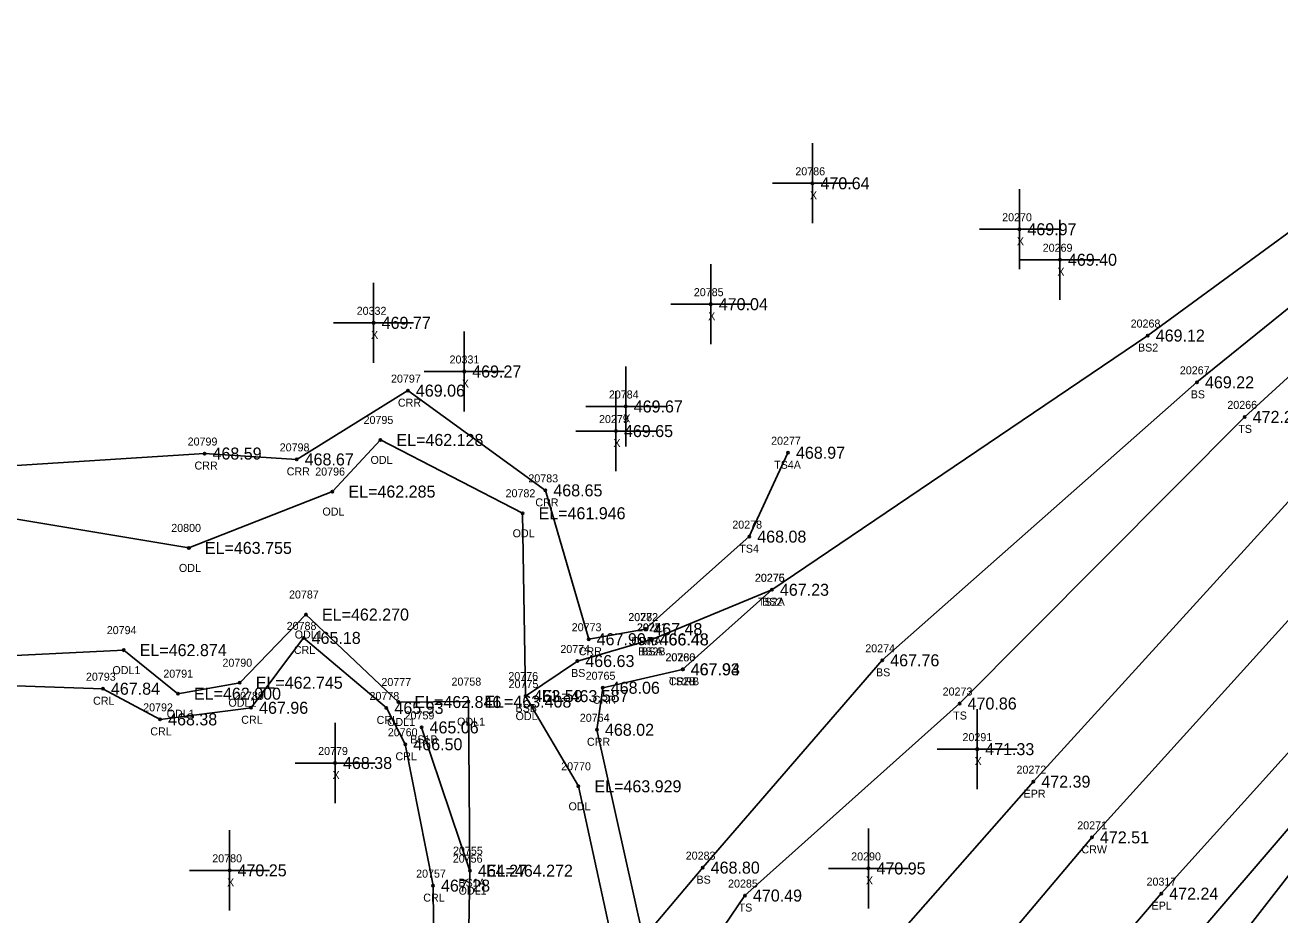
# Model space of a CAD drawing. Extents: x 1741010 to 1742139, y 749382 to 750625.
# Drawn here: x 1741509 to 1741665.8, y 750105.8 to 750217 of the extents above; entities that cross this region are included whole.
import ezdxf

# ---------------------------------------------------------------- set-up
doc = ezdxf.new("R2010")
doc.units = 0
for name, color, linetype in [('RD_DTM_BkLn1', 7, 'Continuous'), ('RD_DTM_BkLn2', 7, 'Continuous'), ('RD_DTM_BkLn_txCode', 7, 'Continuous'), ('RD_EX_H2O', 7, 'Continuous'), ('RD_EX_H2O_txCode', 7, 'Continuous'), ('RD_EX_Misc', 7, 'Continuous'), ('RD_EX_Misc_txCode', 7, 'Continuous'), ('RD_EX_Road', 7, 'Continuous'), ('RD_EX_Road_txCode', 7, 'Continuous'), ('RD_EX_TX_H2O_ELEV', 7, 'Continuous'), ('RD_EX_TX_Misc_ELEV', 7, 'Continuous'), ('RD_EX_TX_Road_ELEV', 7, 'Continuous'), ('RD_HC_Survey_ELEV', 7, 'Continuous'), ('RD_HC_Survey_txCode', 7, 'Continuous'), ('RD_SMD_Locator', 7, 'Continuous')]:
    doc.layers.add(name, color=color, linetype=linetype)

msp = doc.modelspace()

# ---------------------------------------------------------------- linework, layer by layer
at = {"layer": 'RD_DTM_BkLn1'}
msp.add_lwpolyline([(1742095.1, 750579.47), (1742056.96, 750547.11), (1742019.74, 750514.22), (1741983.45, 750480.17), (1741948.01, 750445.01), (1741913.15, 750409.3), (1741879.03, 750372.99), (1741811.59, 750300.09), (1741743.65, 750226.52), (1741676.29, 750153.06), (1741642.32, 750115.53), (1741610.32, 750077.63)], dxfattribs=at)
at = {"layer": 'RD_DTM_BkLn2'}
for p, q in [((1741602.32, 750146.46), (1741591.19, 750136.53)), ((1741564.57, 750111.37), (1741558.53, 750129.27))]:
    msp.add_line(p, q, dxfattribs=at)
for points in [[(1742105.6, 750567.48), (1742094.25, 750560.49), (1742091.64, 750555.7), (1742067.93, 750534.94), (1742031.73, 750501.95), (1741994.85, 750467.63), (1741959.82, 750432.06), (1741925.8, 750396.31), (1741891.25, 750362.62), (1741824.36, 750287.7), (1741756.44, 750214.6), (1741688.69, 750142.04), (1741655.55, 750103.43), (1741644.64, 750083.31), (1741626.06, 750060.3), (1741620, 750055.3), (1741614.97, 750059.12), (1741617.5, 750064.27), (1741619.23, 750067.96)], [(1742107.37, 750564.98), (1742099.21, 750558.66), (1742095.99, 750559.5), (1742095.15, 750554.39), (1742069.73, 750532.61), (1742034.06, 750499.81), (1741997.6, 750464.99), (1741961.88, 750429.54), (1741928.13, 750394.17), (1741895.34, 750359.02), (1741826.5, 750286.36), (1741758.73, 750213.29), (1741690.1, 750140.59), (1741658.36, 750099.77), (1741650.43, 750077.87), (1741632.9, 750061.59), (1741621.97, 750051.56), (1741618.99, 750048.78), (1741611.88, 750047.79)], [(1741687.02, 750214.18), (1741699.03, 750211.31), (1741701.37, 750206.33), (1741693.87, 750197.73), (1741661.42, 750168.06), (1741625.78, 750132.25), (1741598.95, 750108.26), (1741594.55, 750101.81), (1741595.44, 750091.73), (1741598, 750085.41), (1741619.23, 750067.96)], [(1741697.46, 750209.37), (1741696.69, 750207.39), (1741687.32, 750198.15), (1741655.45, 750172.38), (1741616.11, 750137.65), (1741593.67, 750111.75), (1741586.25, 750102.97)], [(1741697.46, 750209.37), (1741695.29, 750209.13), (1741682.34, 750202.39), (1741649.3, 750178.22), (1741602.32, 750146.46), (1741587.3, 750140.26)], [(1741604.33, 750163.58), (1741599.49, 750153.1), (1741586.49, 750141.54)], [(1741587.27, 750140.26), (1741578, 750137.56), (1741571.53, 750133.18)]]:
    msp.add_lwpolyline(points, dxfattribs=at)
at = {"layer": 'RD_EX_H2O'}
for points in [[(1741577.19, 750059.87), (1741574.31, 750069.19), (1741563.25, 750082.19), (1741560.12, 750095.32), (1741559.96, 750109.5), (1741556.5, 750127.16), (1741554.14, 750131.7), (1741543.79, 750140.45), (1741537.22, 750131.72), (1741525.85, 750130.27), (1741518.7, 750134.1), (1741490.89, 750135.06), (1741436.94, 750142.19), (1741375.71, 750163.12), (1741339.37, 750188.79), (1741331.64, 750190.2), (1741328.64, 750186.11), (1741320.24, 750158.32), (1741318.27, 750146.83), (1741309.48, 750135.97), (1741304.66, 750127.91)], [(1741586.49, 750141.56), (1741579.42, 750140.28), (1741574, 750158.88), (1741556.82, 750171.34), (1741542.92, 750162.75), (1741531.4, 750163.48), (1741496.74, 750161.28)], [(1741614.56, 750040.31), (1741609.32, 750045.96), (1741610.78, 750055.8), (1741591.38, 750076.1), (1741585.44, 750084.46), (1741582.64, 750101.29), (1741578.14, 750121.91), (1741571.53, 750133.18), (1741571.15, 750156.02), (1741553.39, 750165.18), (1741547.39, 750158.73), (1741529.44, 750151.69), (1741495.88, 750157.28)], [(1741605.22, 750035.39), (1741604.28, 750042.48), (1741585.13, 750064.77), (1741582.99, 750072.66), (1741567.25, 750084.11), (1741564.22, 750092.13), (1741564.57, 750111.37), (1741564.38, 750132.49), (1741555.63, 750132.44), (1741544.08, 750143.37), (1741535.8, 750134.85), (1741528.08, 750133.48), (1741521.3, 750138.92), (1741491.52, 750137.44)], [(1741597.3, 750084.84), (1741591, 750089.11), (1741586.21, 750103), (1741580.45, 750128.97), (1741581.18, 750134.22), (1741591.16, 750136.52)]]:
    msp.add_lwpolyline(points, dxfattribs=at)
at = {"layer": 'RD_EX_Misc'}
for p, q in [((1741607.39, 750192.24), (1741607.39, 750202.24)), ((1741602.39, 750197.24), (1741612.39, 750197.24)), ((1741633.26, 750186.5), (1741633.26, 750196.5)), ((1741628.26, 750191.5), (1741638.26, 750191.5)), ((1741638.32, 750182.69), (1741638.32, 750192.69)), ((1741594.68, 750177.14), (1741594.68, 750187.14)), ((1741633.32, 750187.69), (1741643.32, 750187.69)), ((1741552.54, 750174.81), (1741552.54, 750184.81)), ((1741589.68, 750182.14), (1741599.68, 750182.14)), ((1741547.54, 750179.81), (1741557.54, 750179.81)), ((1741563.86, 750168.73), (1741563.86, 750178.73)), ((1741584.05, 750164.36), (1741584.05, 750174.36)), ((1741558.86, 750173.73), (1741568.86, 750173.73)), ((1741582.83, 750161.29), (1741582.83, 750171.29)), ((1741579.05, 750169.36), (1741589.05, 750169.36)), ((1741577.83, 750166.29), (1741587.83, 750166.29)), ((1741627.98, 750121.55), (1741627.98, 750131.55)), ((1741547.71, 750119.82), (1741547.71, 750129.82)), ((1741622.98, 750126.55), (1741632.98, 750126.55)), ((1741542.71, 750124.82), (1741552.71, 750124.82)), ((1741534.53, 750106.41), (1741534.53, 750116.41)), ((1741614.39, 750106.65), (1741614.39, 750116.65)), ((1741529.53, 750111.41), (1741539.53, 750111.41)), ((1741609.39, 750111.65), (1741619.39, 750111.65))]:
    msp.add_line(p, q, dxfattribs=at)
at = {"layer": 'RD_EX_Road'}
for points in [[(1742095.24, 750593.27), (1742088.27, 750587.97), (1742078.23, 750580.89), (1742049.13, 750555.21), (1742012.94, 750522.73), (1741975.54, 750488.03), (1741940.71, 750452.82), (1741916.22, 750428.67), (1741904.72, 750416.99), (1741884.38, 750395.02), (1741870.75, 750380.27), (1741817.36, 750322.98), (1741803.89, 750307.66), (1741783.86, 750287.33), (1741735.44, 750234.07), (1741718.84, 750214.98), (1741710.25, 750205.58), (1741668.97, 750159.8), (1741635, 750122.49), (1741604.35, 750087.7), (1741600.63, 750085.47)], [(1742102.43, 750570.61), (1742093.26, 750562.71), (1742064.72, 750538.42), (1742027.92, 750505.65), (1741991.25, 750471.83), (1741956.32, 750436.98), (1741921.43, 750401.39), (1741886.79, 750364.93), (1741819.64, 750292.67), (1741751.78, 750219.01), (1741684.42, 750145.59), (1741650.98, 750108.5), (1741637.17, 750092.42), (1741621.17, 750073.94), (1741621.31, 750072.22), (1741619.24, 750070.27)]]:
    msp.add_lwpolyline(points, dxfattribs=at)
at = {"layer": 'RD_SMD_Locator'}
for centre in [(1741607.39, 750197.24), (1741633.26, 750191.5), (1741638.32, 750187.69), (1741594.68, 750182.14), (1741552.54, 750179.81), (1741649.3, 750178.22), (1741563.86, 750173.73), (1741655.45, 750172.38), (1741556.82, 750171.34), (1741584.05, 750169.36), (1741661.42, 750168.06), (1741582.83, 750166.29), (1741553.39, 750165.18), (1741531.4, 750163.48), (1741604.33, 750163.58), (1741542.92, 750162.75), (1741547.39, 750158.73), (1741574, 750158.88), (1741571.15, 750156.02), (1741599.49, 750153.1), (1741529.44, 750151.69), (1741602.32, 750146.46), (1741602.32, 750146.46), (1741544.08, 750143.37), (1741586.49, 750141.56), (1741586.49, 750141.54), (1741543.79, 750140.45), (1741579.42, 750140.28), (1741587.27, 750140.26), (1741587.3, 750140.26), (1741521.3, 750138.92), (1741578, 750137.56), (1741591.16, 750136.52), (1741591.19, 750136.53), (1741616.11, 750137.65), (1741535.8, 750134.85), (1741518.7, 750134.1), (1741528.08, 750133.48), (1741571.53, 750133.18), (1741571.53, 750133.18), (1741581.18, 750134.22), (1741537.22, 750131.72), (1741554.14, 750131.7), (1741555.63, 750132.44), (1741564.38, 750132.49), (1741625.78, 750132.25), (1741525.85, 750130.27), (1741558.53, 750129.27), (1741580.45, 750128.97), (1741556.5, 750127.16), (1741627.98, 750126.55), (1741547.71, 750124.82), (1741635, 750122.49), (1741578.14, 750121.91), (1741642.32, 750115.53), (1741534.53, 750111.41), (1741564.57, 750111.37), (1741564.57, 750111.37), (1741593.67, 750111.75), (1741614.39, 750111.65), (1741559.96, 750109.5), (1741598.95, 750108.26), (1741650.98, 750108.5)]:
    msp.add_circle(centre, 0.15, dxfattribs=at)

# ---------------------------------------------------------------- texts
at = {"layer": 'RD_DTM_BkLn_txCode'}
for s, p in [('20268', (1741647.16, 750179.22)), ('BS2', (1741648.08, 750176.22)), ('20267', (1741653.31, 750173.38)), ('BS', (1741654.67, 750170.38)), ('20266', (1741659.25, 750169.06)), ('TS', (1741660.62, 750166.06)), ('20277', (1741602.22, 750164.58)), ('TS4A', (1741602.6, 750161.58)), ('20278', (1741597.37, 750154.1)), ('TS4', (1741598.24, 750151.1)), ('20276', (1741600.18, 750147.46)), ('20275', (1741600.21, 750147.46)), ('TS2A', (1741600.59, 750144.46)), ('BS2', (1741601.1, 750144.46)), ('20282', (1741584.37, 750142.54)), ('20771', (1741585.43, 750141.26)), ('20281', (1741585.47, 750141.26)), ('TS4B', (1741584.77, 750139.54)), ('20274', (1741613.99, 750138.65)), ('20774', (1741575.88, 750138.56)), ('BS2B', (1741585.6, 750138.26)), ('BSA', (1741586, 750138.26)), ('20280', (1741589.03, 750137.53)), ('BS', (1741577.22, 750135.56)), ('BS', (1741615.33, 750135.65)), ('20775', (1741569.41, 750134.18)), ('TS2B', (1741589.48, 750134.53)), ('20273', (1741623.66, 750133.25)), ('BSB', (1741570.27, 750131.18)), ('20759', (1741556.41, 750130.27)), ('TS', (1741624.98, 750130.25)), ('BS1B', (1741557.11, 750127.27)), ('20756', (1741562.43, 750112.37)), ('20283', (1741591.55, 750112.75)), ('BS1A', (1741563.14, 750109.37)), ('BS', (1741592.89, 750109.75)), ('20285', (1741596.84, 750109.26)), ('TS', (1741598.16, 750106.26))]:
    msp.add_text(s, height=1, dxfattribs=at).set_placement(p)
at = {"layer": 'RD_EX_H2O_txCode'}
for s, p in [('20797', (1741554.71, 750172.34)), ('CRR', (1741555.57, 750169.34)), ('20795', (1741551.28, 750167.18)), ('20799', (1741529.29, 750164.48)), ('20798', (1741540.8, 750163.75)), ('ODL', (1741552.15, 750162.18)), ('CRR', (1741530.15, 750161.48)), ('CRR', (1741541.67, 750160.75)), ('20796', (1741545.24, 750160.73)), ('20783', (1741571.88, 750159.88)), ('20782', (1741569.03, 750158.02)), ('CRR', (1741572.75, 750156.88)), ('ODL', (1741546.14, 750155.73)), ('20800', (1741527.24, 750153.69)), ('ODL', (1741569.91, 750153.02)), ('ODL', (1741528.2, 750148.69)), ('20787', (1741541.96, 750145.37)), ('20772', (1741584.37, 750142.56)), ('20794', (1741519.18, 750140.92)), ('20788', (1741541.67, 750141.45)), ('ODL1', (1741542.67, 750140.37)), ('20773', (1741577.3, 750141.28)), ('CRRA', (1741584.75, 750139.56)), ('CRL', (1741542.56, 750138.45)), ('CRR', (1741578.17, 750138.28)), ('20766', (1741589, 750137.52)), ('ODL1', (1741519.89, 750135.92)), ('20791', (1741526.25, 750135.48)), ('20790', (1741533.64, 750136.85)), ('20793', (1741516.58, 750135.1)), ('20777', (1741553.51, 750134.44)), ('20758', (1741562.27, 750134.49)), ('20776', (1741569.38, 750135.18)), ('20765', (1741579.04, 750135.22)), ('CRRB', (1741589.44, 750134.52)), ('20789', (1741535.1, 750132.72)), ('20778', (1741552.02, 750132.7)), ('CRL', (1741517.47, 750132.1)), ('20792', (1741523.73, 750131.27)), ('ODL1', (1741534.39, 750131.85)), ('CRR', (1741579.93, 750132.22)), ('ODL1', (1741526.67, 750130.48)), ('CRL', (1741535.99, 750129.72)), ('CRL', (1741552.91, 750129.7)), ('ODL1', (1741554.22, 750129.44)), ('ODL1', (1741562.97, 750129.49)), ('ODL', (1741570.28, 750130.18)), ('20764', (1741578.31, 750129.97)), ('CRL', (1741524.62, 750128.27)), ('20760', (1741554.31, 750128.16)), ('CRR', (1741579.2, 750126.97)), ('CRL', (1741555.27, 750125.16)), ('20770', (1741575.98, 750123.91)), ('ODL', (1741576.9, 750118.91)), ('20755', (1741562.46, 750113.37)), ('20757', (1741557.85, 750110.5)), ('CRL', (1741558.74, 750107.5)), ('ODL1', (1741563.16, 750108.37))]:
    msp.add_text(s, height=1, dxfattribs=at).set_placement(p)
at = {"layer": 'RD_EX_Misc_txCode'}
for s, p in [('20786', (1741605.25, 750198.24)), ('X', (1741607.08, 750195.24)), ('20270', (1741631.1, 750192.5)), ('X', (1741632.94, 750189.5)), ('20269', (1741636.17, 750188.69)), ('X', (1741638, 750185.69)), ('20785', (1741592.56, 750183.14)), ('20332', (1741550.42, 750180.81)), ('X', (1741594.36, 750180.14)), ('X', (1741552.22, 750177.81)), ('20331', (1741562.03, 750174.73)), ('X', (1741563.55, 750171.73)), ('20784', (1741581.94, 750170.36)), ('20279', (1741580.71, 750167.29)), ('X', (1741583.74, 750167.36)), ('X', (1741582.51, 750164.29)), ('20291', (1741626.14, 750127.55)), ('20779', (1741545.6, 750125.82)), ('X', (1741627.66, 750124.55)), ('X', (1741547.4, 750122.82)), ('20780', (1741532.37, 750112.41)), ('20290', (1741612.23, 750112.65)), ('X', (1741534.22, 750109.41)), ('X', (1741614.07, 750109.65))]:
    msp.add_text(s, height=1, dxfattribs=at).set_placement(p)
at = {"layer": 'RD_EX_Road_txCode'}
for s, p in [('20272', (1741632.89, 750123.49)), ('EPR', (1741633.78, 750120.49)), ('20317', (1741649.15, 750109.5)), ('EPL', (1741649.78, 750106.5))]:
    msp.add_text(s, height=1, dxfattribs=at).set_placement(p)
at = {"layer": 'RD_EX_TX_H2O_ELEV'}
for s, p in [('469.06', (1741557.82, 750170.59)), ('EL=462.128', (1741555.39, 750164.43)), ('468.59', (1741532.4, 750162.73)), ('468.67', (1741543.92, 750162)), ('EL=462.285', (1741549.39, 750157.98)), ('468.65', (1741575, 750158.13)), ('EL=461.946', (1741573.15, 750155.27)), ('EL=463.755', (1741531.44, 750150.94)), ('EL=462.270', (1741546.08, 750142.62)), ('465.18', (1741544.79, 750139.7)), ('467.48', (1741587.49, 750140.81)), ('EL=462.874', (1741523.3, 750138.17)), ('467.90', (1741580.42, 750139.53)), ('467.93', (1741592.16, 750135.77)), ('467.84', (1741519.7, 750133.35)), ('EL=462.745', (1741537.8, 750134.1)), ('468.06', (1741582.18, 750133.47)), ('EL=462.000', (1741530.08, 750132.73)), ('EL=463.587', (1741573.53, 750132.43)), ('467.96', (1741538.22, 750130.97)), ('465.93', (1741555.14, 750130.95)), ('EL=462.846', (1741557.63, 750131.69)), ('EL=463.408', (1741566.38, 750131.74)), ('468.38', (1741526.85, 750129.52)), ('468.02', (1741581.45, 750128.22)), ('466.50', (1741557.5, 750126.41)), ('EL=463.929', (1741580.14, 750121.16)), ('EL=464.272', (1741566.57, 750110.62)), ('467.28', (1741560.96, 750108.75))]:
    msp.add_text(s, height=1.5, dxfattribs=at).set_placement(p)
at = {"layer": 'RD_EX_TX_Misc_ELEV'}
for s, p in [('470.64', (1741608.39, 750196.49)), ('469.97', (1741634.26, 750190.75)), ('469.40', (1741639.32, 750186.94)), ('470.04', (1741595.68, 750181.39)), ('469.77', (1741553.54, 750179.06)), ('469.12', (1741650.3, 750177.47)), ('469.27', (1741564.86, 750172.98)), ('469.22', (1741656.45, 750171.63)), ('469.67', (1741585.05, 750168.61)), ('472.26', (1741662.42, 750167.31)), ('469.65', (1741583.83, 750165.54)), ('468.97', (1741605.33, 750162.83)), ('468.08', (1741600.49, 750152.35)), ('467.23', (1741603.32, 750145.71)), ('467.23', (1741603.32, 750145.71)), ('467.48', (1741587.49, 750140.79)), ('466.48', (1741588.27, 750139.51)), ('466.48', (1741588.3, 750139.51)), ('466.63', (1741579, 750136.81)), ('467.76', (1741617.11, 750136.9)), ('467.94', (1741592.19, 750135.78)), ('463.59', (1741572.53, 750132.43)), ('470.86', (1741626.78, 750131.5)), ('465.06', (1741559.53, 750128.52)), ('471.33', (1741628.98, 750125.8)), ('468.38', (1741548.71, 750124.07)), ('470.25', (1741535.53, 750110.66)), ('464.27', (1741565.57, 750110.62)), ('468.80', (1741594.67, 750111)), ('470.95', (1741615.39, 750110.9)), ('470.49', (1741599.95, 750107.51))]:
    msp.add_text(s, height=1.5, dxfattribs=at).set_placement(p)
at = {"layer": 'RD_EX_TX_Road_ELEV'}
for s, p in [('472.39', (1741636, 750121.74)), ('472.24', (1741651.98, 750107.75))]:
    msp.add_text(s, height=1.5, dxfattribs=at).set_placement(p)
at = {"layer": 'RD_HC_Survey_ELEV'}
msp.add_text('472.51', height=1.5, dxfattribs=at).set_placement((1741643.32, 750114.78))
at = {"layer": 'RD_HC_Survey_txCode'}
for s, p in [('20271', (1741640.49, 750116.53)), ('CRW', (1741641.01, 750113.53))]:
    msp.add_text(s, height=1, dxfattribs=at).set_placement(p)

doc.saveas('drawing.dxf')
